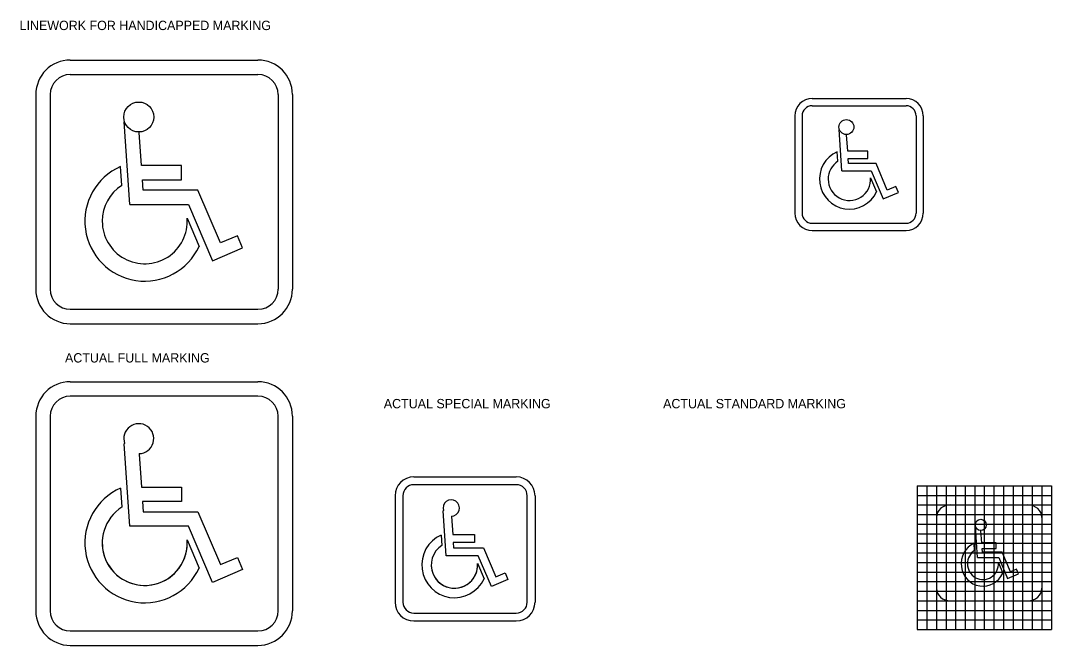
# Model space of a CAD drawing. Extents: x 49948.7 to 50021, y 49977 to 50017.6.
# Drawn here: x 49948.66 to 49984.52, y 49995.91 to 50017.64 of the extents above; entities that cross this region are included whole.
import ezdxf

# ---------------------------------------------------------------- set-up
doc = ezdxf.new("R2010")
doc.units = 0
for name, color, linetype in [('Level 1', 7, 'Continuous'), ('Level 3', 7, 'Continuous'), ('Level 9', 7, 'Continuous')]:
    doc.layers.add(name, color=color, linetype=linetype)

msp = doc.modelspace()

# ---------------------------------------------------------------- linework, layer by layer
at = {"layer": 'Level 1'}
for p, q in [((49950.385, 50005.082), (49956.917, 50005.082)), ((49949.185, 50003.882), (49949.185, 49997.115)), ((49958.117, 50003.882), (49958.117, 49997.115)), ((49962.34, 50001.774), (49965.903, 50001.774)), ((49961.686, 50001.118), (49961.686, 49997.419)), ((49966.558, 50001.119), (49966.558, 49997.419)), ((49962.34, 49996.763), (49965.903, 49996.763)), ((49950.385, 49995.915), (49956.917, 49995.915))]:
    msp.add_line(p, q, dxfattribs=at)
for centre, start, end in [((49950.385, 50003.882), 90, 180), ((49956.917, 50003.882), 0, 90), ((49950.385, 49997.115), 180, 270), ((49956.917, 49997.115), 270, 0)]:
    msp.add_arc(centre, 1.2, start, end, dxfattribs=at)
for centre, major_axis, start_param, end_param in [((49962.34, 50001.118), (0, 0.656), 0, 1.570796), ((49965.903, 50001.118), (0, 0.656), 4.712389, 6.283185), ((49962.34, 49997.419), (0, -0.656), 4.712389, 6.283185), ((49965.903, 49997.419), (0, -0.656), 0, 1.570796)]:
    msp.add_ellipse(centre, major_axis=major_axis, ratio=0.997783, start_param=start_param, end_param=end_param, dxfattribs=at)
at = {"layer": 'Level 3'}
for p, q in [((49950.385, 50016.268), (49956.917, 50016.268)), ((49950.385, 50015.768), (49956.917, 50015.768)), ((49949.185, 50015.068), (49949.185, 50008.301)), ((49949.685, 50015.068), (49949.685, 50008.301)), ((49957.617, 50015.069), (49957.617, 50008.301)), ((49958.117, 50015.069), (49958.117, 50008.301)), ((49976.201, 50014.929), (49979.467, 50014.929)), ((49976.201, 50014.679), (49979.467, 50014.679)), ((49975.601, 50014.329), (49975.601, 50010.946)), ((49975.851, 50014.329), (49975.851, 50010.946)), ((49979.817, 50014.33), (49979.817, 50010.946)), ((49980.067, 50014.33), (49980.067, 50010.946)), ((49952.457, 50011.248), (49952.256, 50014.116)), ((49977.237, 50012.419), (49977.136, 50013.853)), ((49952.863, 50012.601), (49952.783, 50013.748)), ((49977.44, 50013.096), (49977.4, 50013.669)), ((49977.099, 50012.75), (49977.076, 50013.08)), ((49978.134, 50013.096), (49977.44, 50013.096)), ((49978.134, 50012.846), (49978.134, 50013.096)), ((49977.47, 50012.669), (49977.457, 50012.846)), ((49977.457, 50012.846), (49978.134, 50012.846)), ((49952.18, 50011.91), (49952.134, 50012.569)), ((49954.252, 50012.601), (49952.863, 50012.601)), ((49954.252, 50012.101), (49954.252, 50012.601)), ((49977.237, 50012.419), (49978.257, 50012.419)), ((49978.423, 50012.669), (49977.47, 50012.669)), ((49978.257, 50012.419), (49978.673, 50011.441)), ((49978.813, 50011.75), (49978.423, 50012.669)), ((49952.923, 50011.747), (49952.898, 50012.101)), ((49952.898, 50012.101), (49954.252, 50012.101)), ((49978.235, 50012.179), (49978.442, 50011.69)), ((49954.829, 50011.747), (49952.923, 50011.747)), ((49955.61, 50009.909), (49954.829, 50011.747)), ((49978.673, 50011.441), (49979.2, 50011.665)), ((49979.11, 50011.876), (49978.813, 50011.75)), ((49979.2, 50011.665), (49979.11, 50011.876)), ((49952.457, 50011.248), (49954.498, 50011.248)), ((49954.498, 50011.248), (49955.329, 50009.291)), ((49954.453, 50010.768), (49954.868, 50009.79)), ((49976.201, 50010.596), (49979.467, 50010.596)), ((49976.201, 50010.346), (49979.467, 50010.346)), ((49956.204, 50010.161), (49955.61, 50009.909)), ((49956.383, 50009.739), (49956.204, 50010.161)), ((49955.329, 50009.291), (49956.383, 50009.739)), ((49950.385, 50007.601), (49956.917, 50007.601)), ((49950.385, 50007.101), (49956.917, 50007.101)), ((49956.917, 50004.582), (49950.385, 50004.582)), ((49949.685, 50003.882), (49949.685, 49997.115)), ((49957.617, 49997.115), (49957.617, 50003.882)), ((49952.457, 50000.061), (49952.256, 50002.929)), ((49952.783, 50002.562), (49952.863, 50001.414)), ((49952.134, 50001.383), (49952.18, 50000.724)), ((49952.863, 50001.414), (49954.252, 50001.414)), ((49954.252, 50001.414), (49954.252, 50000.914)), ((49965.903, 50001.501), (49962.34, 50001.501)), ((49954.252, 50000.914), (49952.898, 50000.914)), ((49952.898, 50000.914), (49952.923, 50000.561)), ((49961.958, 50001.118), (49961.958, 49997.419)), ((49966.285, 49997.419), (49966.285, 50001.118)), ((49952.923, 50000.561), (49954.829, 50000.561)), ((49954.829, 50000.561), (49955.61, 49998.722)), ((49963.47, 49999.03), (49963.361, 50000.597)), ((49981.017, 50000.798), (49983.699, 50000.798)), ((49963.648, 50000.396), (49963.692, 49999.769)), ((49980.525, 50000.361), (49980.525, 49997.901)), ((49984.191, 50000.362), (49984.191, 49997.901)), ((49954.498, 50000.061), (49952.457, 50000.061)), ((49955.329, 49998.105), (49954.498, 50000.061)), ((49981.954, 49998.969), (49981.881, 50000.04)), ((49982.101, 49999.475), (49982.072, 49999.903)), ((49954.453, 49999.582), (49954.868, 49998.603)), ((49963.294, 49999.752), (49963.319, 49999.392)), ((49963.692, 49999.769), (49964.449, 49999.769)), ((49964.449, 49999.496), (49963.711, 49999.496)), ((49963.711, 49999.496), (49963.724, 49999.303)), ((49964.449, 49999.769), (49964.449, 49999.496)), ((49981.853, 49999.217), (49981.837, 49999.463)), ((49982.607, 49999.475), (49982.101, 49999.475)), ((49982.607, 49999.288), (49982.607, 49999.475)), ((49963.724, 49999.303), (49964.764, 49999.303)), ((49964.764, 49999.303), (49965.19, 49998.298)), ((49982.123, 49999.156), (49982.114, 49999.288)), ((49982.114, 49999.288), (49982.607, 49999.288)), ((49982.816, 49999.156), (49982.123, 49999.156)), ((49983.1, 49998.47), (49982.816, 49999.156)), ((49955.61, 49998.722), (49956.204, 49998.975)), ((49956.204, 49998.975), (49956.383, 49998.553)), ((49964.584, 49999.03), (49963.47, 49999.03)), ((49964.559, 49998.768), (49964.786, 49998.233)), ((49965.037, 49997.96), (49964.584, 49999.03)), ((49981.954, 49998.969), (49982.696, 49998.969)), ((49982.68, 49998.791), (49982.831, 49998.425)), ((49982.696, 49998.969), (49982.998, 49998.239)), ((49956.383, 49998.553), (49955.329, 49998.105)), ((49965.19, 49998.298), (49965.514, 49998.436)), ((49965.514, 49998.436), (49965.612, 49998.205)), ((49982.998, 49998.239), (49983.382, 49998.406)), ((49983.316, 49998.564), (49983.1, 49998.47)), ((49983.382, 49998.406), (49983.316, 49998.564)), ((49965.612, 49998.205), (49965.037, 49997.96)), ((49981.017, 49997.464), (49983.699, 49997.464)), ((49962.34, 49997.036), (49965.903, 49997.036)), ((49950.385, 49996.415), (49956.917, 49996.415))]:
    msp.add_line(p, q, dxfattribs=at)
for points in [[(49952.256, 50002.929), (49952.276, 50002.936)], [(49952.782, 50002.582), (49952.783, 50002.562)], [(49963.361, 50000.597), (49963.372, 50000.601)], [(49963.648, 50000.408), (49963.648, 50000.396)]]:
    msp.add_lwpolyline(points, dxfattribs=at)
for centre, radius in [((49952.769, 50014.289), 0.521), ((49977.393, 50013.94), 0.26)]:
    msp.add_circle(centre, radius, dxfattribs=at)
for centre, radius, start, end in [((49950.385, 50015.068), 1.2, 90, 180), ((49956.917, 50015.068), 1.2, 0, 90), ((49950.385, 50015.068), 0.7, 90, 180), ((49956.917, 50015.068), 0.7, 0, 90), ((49976.201, 50014.329), 0.6, 90, 180), ((49979.467, 50014.329), 0.6, 0, 90), ((49976.201, 50014.329), 0.35, 90, 180), ((49979.467, 50014.329), 0.35, 0, 90), ((49977.497, 50012.127), 1.042, 113.8784, 335.1731), ((49977.497, 50012.127), 0.74, 122.6109, 180), ((49952.977, 50010.664), 2.083, 113.8784, 335.1731), ((49977.497, 50012.127), 0.74, 180, 4.0318), ((49952.977, 50010.664), 1.479, 122.6109, 180), ((49976.201, 50010.946), 0.6, 180, 270), ((49976.201, 50010.946), 0.35, 180, 270), ((49979.467, 50010.946), 0.6, 270, 0), ((49979.467, 50010.946), 0.35, 270, 0), ((49952.977, 50010.664), 1.479, 180, 4.0318), ((49950.385, 50008.301), 1.2, 180, 270), ((49950.385, 50008.301), 0.7, 180, 270), ((49956.917, 50008.301), 1.2, 270, 0), ((49956.917, 50008.301), 0.7, 270, 0), ((49950.385, 50003.882), 0.7, 90, 180), ((49956.917, 50003.882), 0.7, 0, 90), ((49952.769, 50003.103), 0.521, 271.4351, 198.7012), ((49952.977, 49999.478), 2.083, 113.8784, 335.1731), ((49952.977, 49999.478), 1.479, 122.6109, 4.0318), ((49952.977, 49999.478), 1.479, 180, 4.0318), ((49950.385, 49997.115), 0.7, 180, 270), ((49956.917, 49997.115), 0.7, 270, 0)]:
    msp.add_arc(centre, radius, start, end, dxfattribs=at)
for centre, major_axis, ratio, start_param, end_param in [((49962.34, 50001.118), (0, 0.383), 0.997783, 0, 1.570796), ((49965.903, 50001.118), (0, 0.383), 0.997783, 4.712389, 6.283185), ((49963.641, 50000.692), (0, 0.285), 0.997783, 3.16664, 8.18038), ((49981.017, 50000.361), (-0.493, 0), 0.885848, 4.712389, 6.283185), ((49983.699, 50000.361), (-0.493, 0), 0.885848, 3.141593, 4.712389), ((49963.754, 49998.711), (0, 1.139), 0.997783, 0.416757, 4.279079), ((49982.143, 49998.752), (0, 0.778), 0.974026, 0.416757, 4.279079), ((49963.754, 49998.711), (0, -0.809), 0.997783, 3.71076, 7.92435), ((49982.143, 49998.752), (0, -0.552), 0.974026, 3.71076, 4.712389), ((49963.754, 49998.711), (0, -0.809), 0.997783, 4.712389, 7.92435), ((49982.143, 49998.752), (0, -0.552), 0.974026, 4.712389, 7.92435), ((49981.017, 49997.901), (0.493, 0), 0.885848, 3.141593, 4.712389), ((49983.699, 49997.901), (0.493, 0), 0.885848, 4.712389, 6.283185), ((49962.34, 49997.419), (0, -0.383), 0.997783, 4.712389, 6.283185), ((49965.903, 49997.419), (0, -0.383), 0.997783, 0, 1.570796)]:
    msp.add_ellipse(centre, major_axis=major_axis, ratio=ratio, start_param=start_param, end_param=end_param, dxfattribs=at)
msp.add_ellipse((49982.067, 50000.105), major_axis=(0, 0.194), ratio=0.974026, dxfattribs=at)
at = {"layer": 'Level 9'}
for p, q in [((49979.858, 50001.464), (49984.525, 50001.464)), ((49979.858, 50001.464), (49979.858, 49996.464)), ((49980.191, 50001.464), (49980.191, 49996.464)), ((49980.525, 50001.464), (49980.525, 49996.464)), ((49980.858, 50001.464), (49980.858, 49996.464)), ((49981.191, 50001.464), (49981.191, 49996.464)), ((49981.525, 50001.464), (49981.525, 49996.464)), ((49981.858, 50001.464), (49981.858, 49996.464)), ((49982.191, 50001.464), (49982.191, 49996.464)), ((49982.525, 50001.464), (49982.525, 49996.464)), ((49982.858, 50001.464), (49982.858, 49996.464)), ((49983.191, 50001.464), (49983.191, 49996.464)), ((49983.525, 50001.464), (49983.525, 49996.464)), ((49983.858, 50001.464), (49983.858, 49996.464)), ((49984.191, 50001.464), (49984.191, 49996.464)), ((49984.525, 50001.464), (49984.525, 49996.464)), ((49979.858, 50001.131), (49984.525, 50001.131)), ((49979.858, 50000.798), (49984.525, 50000.798)), ((49979.858, 50000.464), (49984.525, 50000.464)), ((49979.858, 50000.131), (49984.525, 50000.131)), ((49979.858, 49999.798), (49984.525, 49999.798)), ((49979.858, 49999.464), (49984.525, 49999.464)), ((49979.858, 49999.131), (49984.525, 49999.131)), ((49979.858, 49998.798), (49984.525, 49998.798)), ((49979.858, 49998.464), (49984.525, 49998.464)), ((49979.858, 49998.131), (49984.525, 49998.131)), ((49979.858, 49997.798), (49984.525, 49997.798)), ((49979.858, 49997.464), (49984.525, 49997.464)), ((49979.858, 49997.131), (49984.525, 49997.131)), ((49979.858, 49996.798), (49984.525, 49996.798)), ((49979.858, 49996.464), (49984.525, 49996.464))]:
    msp.add_line(p, q, dxfattribs=at)

# ---------------------------------------------------------------- texts
at = {"layer": 'Level 3'}
for s, p in [('LINEWORK FOR HANDICAPPED MARKING', (49948.622, 50017.312)), ('ACTUAL FULL MARKING ', (49950.201, 50005.752)), ('ACTUAL SPECIAL MARKING', (49961.295, 50004.16)), ('ACTUAL STANDARD MARKING', (49971.014, 50004.16))]:
    msp.add_text(s, height=0.32425, dxfattribs=at).set_placement(p)

doc.saveas('drawing.dxf')
